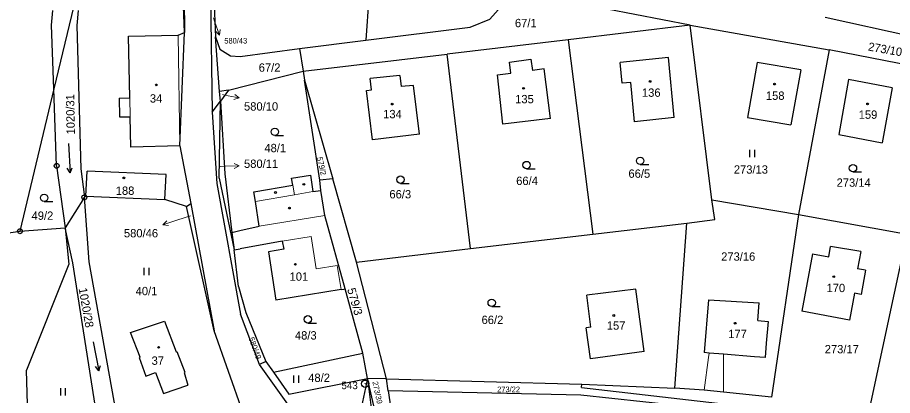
# Model space of a CAD drawing. Extents: x -601131 to -597152, y -1058536 to -1055911.
# Drawn here: x -599468.7 to -599290.5, y -1057278.4 to -1057201.3 of the extents above; entities that cross this region are included whole.
import ezdxf
from ezdxf.enums import TextEntityAlignment as Align

# ---------------------------------------------------------------- set-up
doc = ezdxf.new("R2010")
doc.units = 0
doc.header["$LTSCALE"] = 0.68
for name, color, linetype, lineweight in [('1', 7, 'Continuous', 25), ('3', 7, 'Continuous', 25), ('4', 7, 'Continuous', 13), ('5', 7, 'Continuous', 25), ('7', 7, 'Continuous', 13), ('8', 7, 'Continuous', 25)]:
    doc.layers.add(name, color=color, linetype=linetype, lineweight=lineweight)
doc.layers.add('2', color=7, linetype='Continuous')

msp = doc.modelspace()

# ---------------------------------------------------------------- linework, layer by layer
at = {"layer": '1'}
for p, q in [((-599395.07, -1057165.74), (-599397.77, -1057205.96)), ((-599434.72, -1057204.36), (-599435.62, -1057180.98)), ((-599434.99, -1057181.12), (-599434.72, -1057204.36)), ((-599429.59, -1057183.22), (-599429.07, -1057220.62)), ((-599429.29, -1057183.18), (-599428.41, -1057205.25)), ((-599455.61, -1057191.95), (-599461.31, -1057215.89)), ((-599372.53, -1057201.69), (-599369.66, -1057198.5)), ((-599461.78, -1057202.87), (-599461.53, -1057199.92)), ((-599456.37, -1057199.92), (-599456.62, -1057203)), ((-599331.73, -1057202.88), (-599348.62, -1057199.67)), ((-599376.55, -1057203.32), (-599372.53, -1057201.69)), ((-599304.24, -1057201.25), (-599280.22, -1057206.58)), ((-599461.31, -1057215.89), (-599461.78, -1057202.87)), ((-599456.62, -1057203), (-599455.8, -1057232.17)), ((-599397.77, -1057205.96), (-599376.55, -1057203.32)), ((-599331.73, -1057202.88), (-599356.59, -1057205.86)), ((-599331.73, -1057202.88), (-599303.41, -1057207.92)), ((-599327.3, -1057238.51), (-599331.73, -1057202.88)), ((-599446.12, -1057205.11), (-599435.99, -1057204.91)), ((-599445.87, -1057217.72), (-599446.12, -1057205.11)), ((-599435.99, -1057204.91), (-599434.72, -1057204.36)), ((-599435.66, -1057227.46), (-599434.72, -1057204.36)), ((-599427.56, -1057216.39), (-599428.41, -1057205.25)), ((-599428.41, -1057205.25), (-599427.51, -1057207.79)), ((-599411.31, -1057207.66), (-599397.77, -1057205.96)), ((-599356.59, -1057205.86), (-599381.25, -1057208.79)), ((-599356.59, -1057205.86), (-599351.57, -1057245.49)), ((-599427.51, -1057207.79), (-599425.33, -1057209.18)), ((-599425.33, -1057209.18), (-599423.36, -1057209.25)), ((-599423.36, -1057209.25), (-599411.31, -1057207.66)), ((-599411.31, -1057207.66), (-599410.55, -1057212.25)), ((-599410.55, -1057212.25), (-599381.25, -1057208.79)), ((-599376.49, -1057248.4), (-599381.25, -1057208.79)), ((-599303.41, -1057207.92), (-599309.65, -1057241.5)), ((-599280.87, -1057212.34), (-599303.41, -1057207.92)), ((-599368.54, -1057210.41), (-599364.16, -1057209.84)), ((-599368.26, -1057212.66), (-599368.54, -1057210.41)), ((-599364.16, -1057209.84), (-599363.88, -1057212.12)), ((-599336.14, -1057209.46), (-599346.01, -1057210.48)), ((-599345.57, -1057214.73), (-599346.01, -1057210.48)), ((-599335, -1057221.69), (-599336.14, -1057209.46)), ((-599318.1, -1057210.51), (-599320.09, -1057221.7)), ((-599309.19, -1057212.02), (-599318.1, -1057210.51)), ((-599425.76, -1057216.16), (-599410.55, -1057212.25)), ((-599410.55, -1057212.25), (-599410.28, -1057214.1)), ((-599370.97, -1057213), (-599368.26, -1057212.66)), ((-599361.48, -1057211.83), (-599363.88, -1057212.12)), ((-599360.2, -1057221.94), (-599361.48, -1057211.83)), ((-599309.19, -1057212.02), (-599311.21, -1057223.18)), ((-599410.28, -1057214.1), (-599404.51, -1057234.22)), ((-599407.16, -1057234.5), (-599410.28, -1057214.1)), ((-599390.86, -1057213.13), (-599396.92, -1057213.8)), ((-599396.66, -1057216.09), (-599396.92, -1057213.8)), ((-599390.86, -1057213.13), (-599390.61, -1057215.39)), ((-599369.88, -1057223.08), (-599370.97, -1057213)), ((-599343.81, -1057214.55), (-599345.57, -1057214.73)), ((-599343.05, -1057222.57), (-599343.81, -1057214.55)), ((-599299.47, -1057213.97), (-599301.5, -1057225.16)), ((-599290.59, -1057215.64), (-599299.47, -1057213.97)), ((-599461.31, -1057215.89), (-599468.22, -1057244.89)), ((-599460.75, -1057231.57), (-599461.31, -1057215.89)), ((-599425.76, -1057216.16), (-599427.56, -1057216.39)), ((-599427.41, -1057218.37), (-599427.56, -1057216.39)), ((-599425.76, -1057216.16), (-599427.41, -1057218.37)), ((-599397.64, -1057216.23), (-599396.66, -1057216.09)), ((-599396.4, -1057226.28), (-599397.64, -1057216.23)), ((-599388.1, -1057215.16), (-599390.61, -1057215.39)), ((-599386.86, -1057225.11), (-599388.1, -1057215.16)), ((-599290.59, -1057215.64), (-599292.61, -1057226.89)), ((-599448.02, -1057217.76), (-599445.87, -1057217.72)), ((-599448.02, -1057217.76), (-599447.92, -1057221.58)), ((-599429.07, -1057220.62), (-599427.41, -1057218.37)), ((-599427.67, -1057234.06), (-599427.41, -1057218.37)), ((-599427.41, -1057218.37), (-599426.52, -1057233.2)), ((-599447.92, -1057221.58), (-599445.76, -1057221.55)), ((-599445.67, -1057227.75), (-599445.76, -1057221.55)), ((-599429.07, -1057220.62), (-599428.15, -1057235.15)), ((-599335, -1057221.69), (-599343.05, -1057222.57)), ((-599320.09, -1057221.7), (-599311.21, -1057223.18)), ((-599360.2, -1057221.94), (-599369.88, -1057223.08)), ((-599386.86, -1057225.11), (-599396.4, -1057226.28)), ((-599301.5, -1057225.16), (-599292.61, -1057226.89)), ((-599435.66, -1057227.46), (-599445.67, -1057227.75)), ((-599435.66, -1057227.46), (-599433.43, -1057239.27)), ((-599460.75, -1057231.57), (-599458.99, -1057244.22)), ((-599455.8, -1057232.17), (-599455.11, -1057237.97)), ((-599454.8, -1057237.71), (-599454.56, -1057232.68)), ((-599438.46, -1057233.36), (-599454.56, -1057232.68)), ((-599438.7, -1057238.45), (-599438.46, -1057233.36)), ((-599427.67, -1057234.06), (-599424.61, -1057248.7)), ((-599426.52, -1057233.2), (-599425.05, -1057245.12)), ((-599412.9, -1057234.08), (-599409.04, -1057233.46)), ((-599412.66, -1057235.47), (-599412.9, -1057234.08)), ((-599409.04, -1057233.46), (-599408.58, -1057236.8)), ((-599404.51, -1057234.22), (-599407.16, -1057234.5)), ((-599399.72, -1057251.16), (-599404.51, -1057234.22)), ((-599428.15, -1057235.15), (-599423.3, -1057261.76)), ((-599420.59, -1057236.83), (-599412.66, -1057235.47)), ((-599406.94, -1057236.58), (-599407.16, -1057234.5)), ((-599454.8, -1057237.71), (-599455.11, -1057237.97)), ((-599454.8, -1057237.71), (-599438.7, -1057238.45)), ((-599420.29, -1057238.85), (-599420.59, -1057236.83)), ((-599408.58, -1057236.8), (-599406.94, -1057236.58)), ((-599406.12, -1057241.7), (-599406.94, -1057236.58)), ((-599455.11, -1057237.97), (-599458.99, -1057244.22)), ((-599454.14, -1057251.12), (-599455.11, -1057237.97)), ((-599434.3, -1057239.86), (-599438.7, -1057238.45)), ((-599434.3, -1057239.86), (-599433.43, -1057239.27)), ((-599433.43, -1057239.27), (-599428.69, -1057265.15)), ((-599419.54, -1057243.86), (-599420.29, -1057238.85)), ((-599327.3, -1057238.51), (-599309.65, -1057241.5)), ((-599326.73, -1057242.52), (-599327.3, -1057238.51)), ((-599428.69, -1057265.15), (-599434.3, -1057239.86)), ((-599402.01, -1057256.63), (-599406.12, -1057241.7)), ((-599351.57, -1057245.49), (-599332.4, -1057243.24)), ((-599334.85, -1057276.88), (-599332.4, -1057243.24)), ((-599332.4, -1057243.24), (-599326.73, -1057242.52)), ((-599309.65, -1057241.5), (-599315.21, -1057278.73)), ((-599309.65, -1057241.5), (-599287.53, -1057245.47)), ((-599496.24, -1057248.99), (-599468.22, -1057244.89)), ((-599468.22, -1057244.89), (-599458.99, -1057244.22)), ((-599457.48, -1057251.31), (-599458.99, -1057244.22)), ((-599458.99, -1057244.22), (-599458.27, -1057251.59)), ((-599425.05, -1057245.12), (-599423.47, -1057244.76)), ((-599423.47, -1057244.76), (-599419.54, -1057243.86)), ((-599425.05, -1057245.12), (-599424.61, -1057248.7)), ((-599376.49, -1057248.4), (-599351.57, -1057245.49)), ((-599295.06, -1057280.63), (-599287.53, -1057245.47)), ((-599424.61, -1057248.7), (-599423.38, -1057248.48)), ((-599414.81, -1057246.92), (-599423.38, -1057248.48)), ((-599414.52, -1057248.51), (-599417.62, -1057249.07)), ((-599414.81, -1057246.92), (-599414.52, -1057248.51)), ((-599399.72, -1057251.16), (-599376.49, -1057248.4)), ((-599303.52, -1057250.11), (-599303.16, -1057247.97)), ((-599297.01, -1057249), (-599303.16, -1057247.97)), ((-599423.7, -1057256.14), (-599424.61, -1057248.7)), ((-599417.62, -1057249.07), (-599416.13, -1057258.96)), ((-599306.81, -1057249.47), (-599308.98, -1057261.17)), ((-599306.81, -1057249.47), (-599303.52, -1057250.11)), ((-599297.01, -1057249), (-599297.66, -1057252.56)), ((-599458.27, -1057251.59), (-599466.89, -1057273.22)), ((-599452.51, -1057283), (-599457.48, -1057251.31)), ((-599448.59, -1057282.13), (-599454.14, -1057251.12)), ((-599393.58, -1057274.97), (-599399.72, -1057251.16)), ((-599296.06, -1057252.85), (-599297.66, -1057252.56)), ((-599296.06, -1057252.85), (-599296.95, -1057257.75)), ((-599423.7, -1057256.14), (-599422.25, -1057261.42)), ((-599402.83, -1057256.78), (-599416.13, -1057258.96)), ((-599402.83, -1057256.78), (-599402.3, -1057256.68)), ((-599402.3, -1057256.68), (-599402.01, -1057256.63)), ((-599398.41, -1057269.72), (-599402.01, -1057256.63)), ((-599342.83, -1057256.68), (-599352.78, -1057257.92)), ((-599341.14, -1057269.41), (-599342.83, -1057256.68)), ((-599298.31, -1057257.5), (-599299.32, -1057263.01)), ((-599296.95, -1057257.75), (-599298.31, -1057257.5)), ((-599351.97, -1057264.45), (-599352.78, -1057257.92)), ((-599328.04, -1057258.84), (-599328.86, -1057269.63)), ((-599328.04, -1057258.84), (-599317.68, -1057259.49)), ((-599317.98, -1057263.09), (-599317.68, -1057259.49)), ((-599419.47, -1057272.04), (-599423.3, -1057261.76)), ((-599422.25, -1057261.42), (-599418.17, -1057271.41)), ((-599299.32, -1057263.01), (-599308.98, -1057261.17)), ((-599445.72, -1057265.53), (-599438.81, -1057263.22)), ((-599438.81, -1057263.22), (-599436.43, -1057269.47)), ((-599351.97, -1057264.45), (-599352.95, -1057264.58)), ((-599352.07, -1057270.92), (-599352.95, -1057264.58)), ((-599443.75, -1057270.55), (-599445.72, -1057265.53)), ((-599422.85, -1057281.74), (-599428.69, -1057265.15)), ((-599316.24, -1057267.68), (-599316.49, -1057270.62)), ((-599436.43, -1057269.47), (-599436.29, -1057269.42)), ((-599436.29, -1057269.42), (-599434.64, -1057273.63)), ((-599416.61, -1057273.63), (-599398.41, -1057269.72)), ((-599397.46, -1057274.9), (-599398.41, -1057269.72)), ((-599341.14, -1057269.41), (-599352.07, -1057270.92)), ((-599327.87, -1057269.71), (-599328.86, -1057269.63)), ((-599324.95, -1057269.94), (-599327.87, -1057269.71)), ((-599318.63, -1057270.45), (-599324.95, -1057269.94)), ((-599443.75, -1057270.55), (-599443.98, -1057270.64)), ((-599443.98, -1057270.64), (-599442.61, -1057274.41)), ((-599418.17, -1057271.41), (-599419.47, -1057272.04)), ((-599418.17, -1057271.41), (-599416.61, -1057273.63)), ((-599316.49, -1057270.62), (-599318.63, -1057270.45)), ((-599466.34, -1057290.2), (-599466.89, -1057273.22)), ((-599411.44, -1057283.19), (-599419.47, -1057272.04)), ((-599442.61, -1057274.41), (-599440.63, -1057273.66)), ((-599440.63, -1057273.66), (-599438.99, -1057277.97)), ((-599434.64, -1057273.63), (-599434.79, -1057273.67)), ((-599434.79, -1057273.67), (-599434.05, -1057276.25)), ((-599416.61, -1057273.63), (-599413.5, -1057278.06)), ((-599413.5, -1057278.06), (-599397.46, -1057274.9)), ((-599397.46, -1057274.9), (-599399.88, -1057286.45)), ((-599393.58, -1057274.97), (-599397.46, -1057274.9)), ((-599394.93, -1057285.61), (-599397.46, -1057274.9)), ((-599397.46, -1057274.9), (-599395.98, -1057286.23)), ((-599393.21, -1057277.43), (-599393.58, -1057274.97)), ((-599393.58, -1057274.97), (-599353.77, -1057276.06)), ((-599438.99, -1057277.97), (-599434.05, -1057276.25)), ((-599353.84, -1057276.72), (-599353.77, -1057276.06)), ((-599353.84, -1057276.72), (-599322.66, -1057280.34)), ((-599353.77, -1057276.06), (-599334.85, -1057276.88)), ((-599328.87, -1057277.3), (-599334.85, -1057276.88)), ((-599393.21, -1057277.43), (-599392.54, -1057281.88)), ((-599353.99, -1057278.29), (-599393.21, -1057277.43)), ((-599328.78, -1057281.02), (-599353.99, -1057278.29)), ((-599324.94, -1057277.69), (-599328.87, -1057277.3)), ((-599315.21, -1057278.73), (-599324.94, -1057277.69))]:
    msp.add_line(p, q, dxfattribs=at)
msp.add_lwpolyline([(-599317.98, -1057263.09), (-599315.87, -1057263.27), (-599316.24, -1057267.68)], dxfattribs=at)
at = {"layer": '3'}
for p, q in [((-599416.303, -1057225.37), (-599414.553, -1057225.37)), ((-599319.561, -1057229.79), (-599319.561, -1057228.29)), ((-599318.56, -1057229.79), (-599318.56, -1057228.29)), ((-599458.031, -1057233.003), (-599458.583, -1057232.054)), ((-599365.053, -1057232.15), (-599363.303, -1057232.15)), ((-599341.903, -1057231.3), (-599340.153, -1057231.3)), ((-599298.593, -1057232.8), (-599296.843, -1057232.8)), ((-599390.743, -1057235.13), (-599388.993, -1057235.13)), ((-599463.313, -1057238.82), (-599461.563, -1057238.82)), ((-599442.931, -1057253.87), (-599442.931, -1057252.37)), ((-599441.93, -1057253.87), (-599441.93, -1057252.37)), ((-599372.153, -1057260.21), (-599370.403, -1057260.21)), ((-599409.593, -1057263.59), (-599407.843, -1057263.59)), ((-599452.143, -1057273.333), (-599452.821, -1057272.47)), ((-599412.451, -1057275.8), (-599412.451, -1057274.3)), ((-599411.45, -1057275.8), (-599411.45, -1057274.3)), ((-599459.921, -1057278.35), (-599459.921, -1057276.85)), ((-599458.92, -1057278.35), (-599458.92, -1057276.85))]:
    msp.add_line(p, q, dxfattribs=at)
for points in [[(-599458.345, -1057227.012), (-599458.031, -1057233.003), (-599457.581, -1057232.001)], [(-599453.288, -1057267.444), (-599452.143, -1057273.333), (-599451.837, -1057272.278)]]:
    msp.add_lwpolyline(points, dxfattribs=at)
for centre in [(-599416.3029, -1057224.6198), (-599365.0529, -1057231.3998), (-599341.9029, -1057230.5498), (-599298.5929, -1057232.0498), (-599390.7429, -1057234.3798), (-599463.3129, -1057238.0698), (-599372.1529, -1057259.4598), (-599409.5929, -1057262.8398)]:
    msp.add_circle(centre, 0.75, dxfattribs=at)
at = {"layer": '4'}
for p, q in [((-599435.66, -1057227.46), (-599435.99, -1057204.91)), ((-599445.87, -1057217.72), (-599445.76, -1057221.55)), ((-599412.32, -1057237.45), (-599412.66, -1057235.47)), ((-599420.29, -1057238.85), (-599412.32, -1057237.45)), ((-599412.32, -1057237.45), (-599408.58, -1057236.8)), ((-599419.54, -1057243.86), (-599406.12, -1057241.7)), ((-599408.93, -1057245.96), (-599414.81, -1057246.92)), ((-599408.93, -1057245.96), (-599407.92, -1057252.52)), ((-599407.92, -1057252.52), (-599403.62, -1057251.86)), ((-599403.62, -1057251.86), (-599402.83, -1057256.78)), ((-599327.99, -1057270.63), (-599327.87, -1057269.71)), ((-599324.95, -1057269.94), (-599324.95, -1057270.76)), ((-599328.87, -1057277.3), (-599327.99, -1057270.63)), ((-599324.95, -1057270.76), (-599324.94, -1057277.69))]:
    msp.add_line(p, q, dxfattribs=at)
at = {"layer": '5'}
for centre in [(-599339.9068, -1057214.3592), (-599314.5468, -1057214.9092), (-599440.4568, -1057215.0692), (-599365.6668, -1057215.7592), (-599392.4068, -1057218.9892), (-599295.6168, -1057218.9392), (-599447.0668, -1057234.0192), (-599410.4168, -1057235.3292), (-599416.1868, -1057236.9992), (-599413.3468, -1057240.1692), (-599412.1368, -1057251.6292), (-599302.4968, -1057254.1392), (-599347.2968, -1057262.0592), (-599322.5768, -1057263.6392), (-599439.9868, -1057268.5492)]:
    msp.add_circle(centre, 0.175, dxfattribs=at)
at = {"layer": '7'}
for p, q in [((-599427.603, -1057204.917), (-599427.456, -1057203.808)), ((-599423.594, -1057217.713), (-599424.482, -1057217.03)), ((-599423.601, -1057231.555), (-599424.619, -1057231.09)), ((-599439.104, -1057243.567), (-599437.997, -1057243.734))]:
    msp.add_line(p, q, dxfattribs=at)
for points in [[(-599428.81, -1057201.42), (-599428.58, -1057202.08), (-599427.603, -1057204.917), (-599428.402, -1057204.134)], [(-599427, -1057217.05), (-599426.54, -1057217.14), (-599423.594, -1057217.713), (-599424.673, -1057218.013)], [(-599427.47, -1057231.69), (-599426.6, -1057231.66), (-599423.601, -1057231.555), (-599424.584, -1057232.091)], [(-599433.49, -1057241.74), (-599436.25, -1057242.64), (-599439.104, -1057243.567), (-599438.306, -1057242.782)]]:
    msp.add_lwpolyline(points, dxfattribs=at)
at = {"layer": '8'}
for centre, radius in [((-599460.75, -1057231.5699), 0.5), ((-599460.75, -1057231.5699), 0.0303), ((-599455.11, -1057237.9699), 0.5), ((-599455.11, -1057237.9699), 0.0303), ((-599468.22, -1057244.8899), 0.5), ((-599468.22, -1057244.8899), 0.0303), ((-599397.92, -1057275.9498), 0.75), ((-599397.92, -1057275.9498), 0.03)]:
    msp.add_circle(centre, radius, dxfattribs=at)

# ---------------------------------------------------------------- texts
at = {"layer": '2'}
for s, height, p in [('67/1', 1.7, (-599367.43, -1057203.314)), ('580/43', 1.14, (-599426.61, -1057206.64)), ('67/2', 1.7, (-599419.6, -1057212.385)), ('136', 1.7, (-599341.56, -1057217.495)), ('158', 1.7, (-599316.32, -1057218.115)), ('34', 1.7, (-599441.77, -1057218.675)), ('135', 1.7, (-599367.38, -1057218.814)), ('580/10', 1.7, (-599422.6, -1057220.305)), ('134', 1.7, (-599394.26, -1057221.865)), ('159', 1.7, (-599297.42, -1057221.975)), ('48/1', 1.7, (-599418.45, -1057228.785)), ('580/11', 1.7, (-599422.6, -1057231.985)), ('66/5', 1.7, (-599344.31, -1057233.995)), ('273/13', 1.7, (-599322.85, -1057233.155)), ('66/4', 1.7, (-599367.17, -1057235.465)), ('273/14', 1.7, (-599301.92, -1057235.824)), ('188', 1.7, (-599448.72, -1057237.475)), ('66/3', 1.7, (-599392.99, -1057238.195)), ('49/2', 1.7, (-599465.86, -1057242.564)), ('273/16', 1.7, (-599325.43, -1057250.895)), ('101', 1.7, (-599413.32, -1057254.975)), ('170', 1.7, (-599303.97, -1057257.295)), ('40/1', 1.7, (-599444.67, -1057257.925)), ('66/2', 1.7, (-599374.22, -1057263.795)), ('157', 1.7, (-599348.72, -1057264.955)), ('48/3', 1.7, (-599412.23, -1057266.955)), ('177', 1.7, (-599324, -1057266.675)), ('273/17', 1.7, (-599304.34, -1057269.765)), ('37', 1.7, (-599441.42, -1057272.104)), ('48/2', 1.7, (-599409.52, -1057275.594)), ('273/22', 1.14, (-599371.05, -1057277.684))]:
    msp.add_text(s, height=height, dxfattribs=at).set_placement(p)
for s, height, rotation, p in [('273/10', 1.7, 350, (-599295.593, -1057208.048)), ('1020/31', 1.7, 91, (-599457.035, -1057225.152)), ('579/2', 1.14, 283, (-599407.777, -1057229.854)), ('1020/28', 1.7, 280, (-599456.278, -1057256.563)), ('579/3', 1.7, 286, (-599401.608, -1057256.717)), ('580/49', 1.14, 290, (-599421.677, -1057266.707)), ('273/39', 1.14, 282, (-599396.458, -1057275.599))]:
    msp.add_text(s, height=height, rotation=rotation, dxfattribs=at).set_placement(p)
msp.add_text('580/46', height=1.7, dxfattribs=at).set_placement((-599440.099, -1057246.135), align=Align.RIGHT)
at = {"layer": '8'}
msp.add_text('543', height=1.5, dxfattribs=at).set_placement((-599399.419, -1057277.067), align=Align.RIGHT)

doc.saveas('drawing.dxf')
